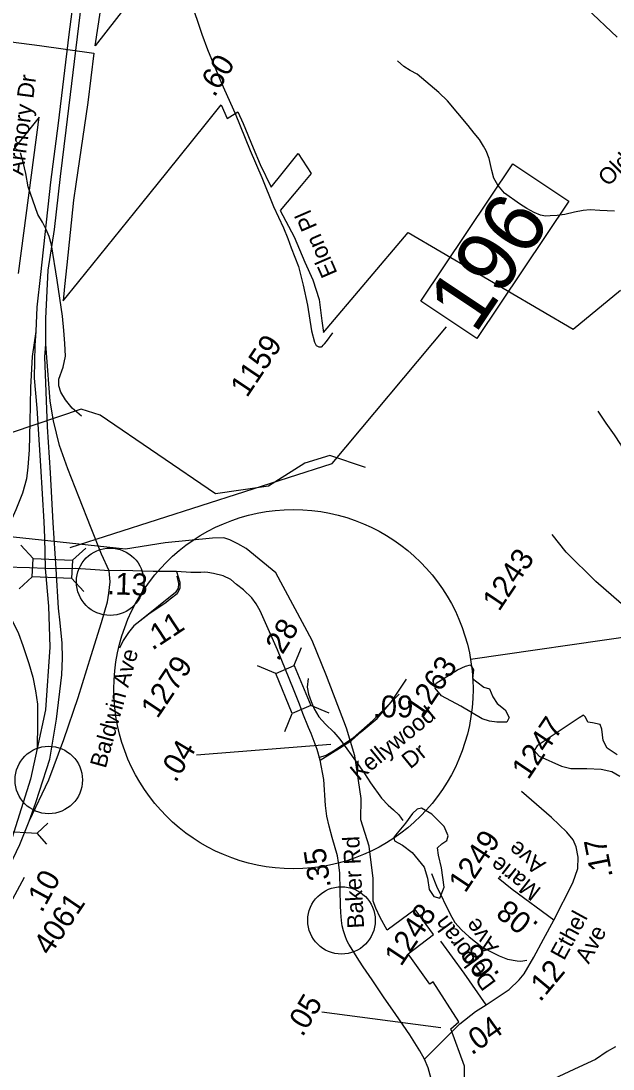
# Model space of a CAD drawing. Extents: x 1715610 to 1720914, y 798298 to 802505.
# Drawn here: x 1715906.1 to 1715979.8, y 799574.8 to 799705.3 of the extents above; entities that cross this region are included whole.
import ezdxf

# ---------------------------------------------------------------- set-up
doc = ezdxf.new("R2010")
doc.units = 0
doc.layers.add('Default', color=7, linetype='Continuous')
doc.layers.add('Prop DSN Text', color=7, linetype='Continuous')

msp = doc.modelspace()

# ---------------------------------------------------------------- linework, layer by layer
at = {"layer": 'Default'}
for p, q in [((1715906.08, 799640.03), (1715907.59, 799638.38)), ((1715912.49, 799638.15), (1715914.14, 799639.66)), ((1715905.84, 799634.58), (1715907.49, 799636.09)), ((1715912.39, 799635.91), (1715913.9, 799634.26)), ((1715940.08, 799625.02), (1715941.02, 799627.29)), ((1715937.81, 799624.07), (1715935.53, 799625.01)), ((1715938.93, 799616.81), (1715939.87, 799619.09)), ((1715944.47, 799619.12), (1715942.19, 799620.06)), ((1715944.68, 799615.21), (1715927.94, 799613.87)), ((1715909.43, 799605.42), (1715908.11, 799604.18)), ((1715903.81, 799604.43), (1715908.11, 799604.18)), ((1715909.28, 799602.8), (1715908.11, 799604.18)), ((1715958.35, 799579.93), (1715943.56, 799581.88))]:
    msp.add_line(p, q, dxfattribs=at)
for points in [[(1715915.87, 799731.82), (1715913.25, 799712.93), (1715912.04, 799703.65), (1715910.72, 799692.59), (1715909.75, 799685.23), (1715908.49, 799673.76), (1715908.04, 799669.68), (1715907.92, 799666.67)], [(1715909.16, 799665.06), (1715909.16, 799668.28), (1715909.48, 799674.3), (1715910.26, 799679.35), (1715910.99, 799685.96), (1715911.72, 799691.71), (1715914.34, 799713.3), (1715916.13, 799723.77)], [(1715921.67, 799710.42), (1715915.32, 799702.24), (1715915.3, 799702.21), (1715916.92, 799712.92)], [(1715921.67, 799710.42), (1715915.32, 799702.24), (1715915.3, 799702.21), (1715916.92, 799712.92)], [(1715927.44, 799707.09), (1715928.05, 799705.29), (1715928.59, 799703.69), (1715929.31, 799701.76), (1715931.05, 799697.56), (1715932.77, 799693.81), (1715934.63, 799689.21), (1715936.09, 799685.85), (1715937.54, 799682.23), (1715938.76, 799679.56), (1715939.33, 799678.24), (1715939.71, 799677.08), (1715940.66, 799674.75), (1715940.94, 799673.59), (1715941.24, 799672.42), (1715941.75, 799669.95), (1715942.25, 799666.72), (1715942.62, 799665.31), (1715942.84, 799664.92), (1715943.19, 799664.72), (1715943.49, 799664.76), (1715943.57, 799664.77), (1715943.72, 799664.94), (1715943.88, 799665.11), (1715944.13, 799665.4), (1715944.92, 799666.5)], [(1715980.31, 799703.3), (1715976.56, 799706.89)], [(1715980.31, 799703.3), (1715976.56, 799706.89)], [(1715900.95, 799703.22), (1715908.4, 799702.28), (1715915.17, 799701.33), (1715914.39, 799695.17), (1715912.92, 799684.99), (1715912.63, 799683), (1715911.79, 799674.96), (1715911.51, 799672.25), (1715911.35, 799670.45), (1715913.3, 799672.88), (1715921.12, 799682.58), (1715924.25, 799686.47), (1715929.19, 799692.6), (1715931.02, 799694.87), (1715931.77, 799693.17), (1715933.08, 799694), (1715933.73, 799692.54)], [(1715900.95, 799703.22), (1715908.4, 799702.28), (1715915.17, 799701.33), (1715914.39, 799695.17), (1715912.92, 799684.99), (1715912.63, 799683), (1715911.79, 799674.96), (1715911.51, 799672.25), (1715911.35, 799670.45), (1715913.3, 799672.88), (1715921.12, 799682.58), (1715924.25, 799686.47), (1715929.19, 799692.6), (1715931.02, 799694.87), (1715931.77, 799693.17), (1715933.08, 799694), (1715933.73, 799692.54)], [(1715980, 799681.64), (1715978.17, 799681.73), (1715976.96, 799681.82), (1715976.1, 799681.72), (1715975.01, 799681.51), (1715973.82, 799681.23), (1715972.87, 799681.08), (1715972, 799681.04), (1715971.41, 799681.03), (1715970.8, 799681.13), (1715969.98, 799681.48), (1715969.07, 799681.99), (1715968.15, 799682.57), (1715966.3, 799683.88), (1715965.46, 799684.88), (1715964.98, 799685.73), (1715964.7, 799686.71), (1715964.39, 799688.19), (1715964, 799689.15), (1715963.7, 799689.72), (1715963.17, 799690.56), (1715962.51, 799691.37), (1715961.78, 799692.3), (1715959.19, 799695.38), (1715958.12, 799696.43), (1715955.4, 799698.7), (1715954.56, 799699.17), (1715953.78, 799699.65), (1715952.96, 799700.38)], [(1715905.79, 799673.89), (1715908.36, 799693.36), (1715901.2, 799684.46)], [(1715905.79, 799673.89), (1715908.36, 799693.36), (1715901.2, 799684.46)], [(1715933.73, 799692.54), (1715934.99, 799689.52), (1715935.86, 799687.44), (1715937.23, 799684.61), (1715938.59, 799686.31), (1715940.6, 799688.83), (1715942.22, 799686.32), (1715940.97, 799684.83), (1715938.37, 799681.7), (1715940.12, 799678.46), (1715941.44, 799675.3), (1715942.44, 799673.08), (1715943.2, 799670.65), (1715943.54, 799667.97), (1715943.77, 799666.51), (1715954.32, 799678.97), (1715974.84, 799666.96), (1715980.75, 799671.8)], [(1715933.73, 799692.54), (1715934.99, 799689.52), (1715935.86, 799687.44), (1715937.23, 799684.61), (1715938.59, 799686.31), (1715940.6, 799688.83), (1715942.22, 799686.32), (1715940.97, 799684.83), (1715938.37, 799681.7), (1715940.12, 799678.46), (1715941.44, 799675.3), (1715942.44, 799673.08), (1715943.2, 799670.65), (1715943.54, 799667.97), (1715943.77, 799666.51), (1715954.32, 799678.97), (1715974.84, 799666.96), (1715980.75, 799671.8)], [(1715913.61, 799656.12), (1715912.45, 799657.12), (1715911.61, 799658.12), (1715911.05, 799659.08), (1715910.81, 799659.88), (1715910.8, 799660.72), (1715911.34, 799662.2), (1715911.64, 799663.57), (1715911.56, 799665.16), (1715911.41, 799666.79), (1715911.24, 799668.54), (1715910.58, 799673.05), (1715909.9, 799677.46), (1715909.59, 799678.47), (1715909.2, 799679.36), (1715908.75, 799680.25), (1715908.16, 799681.23), (1715906.98, 799684.67), (1715906.67, 799686.31), (1715906.34, 799687.75), (1715906.03, 799688.91)], [(1715912.21, 799639.76), (1715944.82, 799650.2), (1715959.07, 799667.23)], [(1715907.92, 799666.67), (1715907.49, 799663.53), (1715907.27, 799659.67), (1715907.19, 799655.36), (1715907.08, 799651.92), (1715906.95, 799649.74), (1715906.77, 799648.31), (1715906.28, 799646.53), (1715905.43, 799644.44), (1715903.95, 799641.06), (1715902.9, 799638.56), (1715902.3, 799637.29)], [(1715907.92, 799666.67), (1715907.82, 799664.89), (1715907.71, 799660.91), (1715907.71, 799660.85), (1715908.04, 799657.12), (1715908.52, 799649.92), (1715908.94, 799642.95), (1715908.99, 799641), (1715909.1, 799637.14)], [(1715910.48, 799637.07), (1715910.1, 799642.82), (1715909.77, 799649.03), (1715909.4, 799654.76), (1715909.04, 799663.48), (1715909.16, 799665.06)], [(1715917.05, 799636.84), (1715916.1, 799638.9), (1715914.82, 799642.14), (1715913.3, 799646.04), (1715911.9, 799649.55), (1715910.86, 799652.43), (1715910.11, 799655.51), (1715909.72, 799657.96), (1715909.58, 799659.61), (1715909.16, 799665.06)], [(1715948.98, 799649.69), (1715944.54, 799651.19), (1715941.43, 799650.24), (1715936.92, 799647.4), (1715930.32, 799646.42), (1715915.93, 799656.24), (1715913.57, 799656.98), (1715905, 799654.05), (1715901.6, 799656.26)], [(1715977.93, 799656.71), (1715978.93, 799655.23), (1715979.95, 799653.8), (1715980.75, 799652.57), (1715981.45, 799651.29), (1715982.12, 799650.11), (1715982.9, 799648.94), (1715984.73, 799646.53), (1715985.55, 799645.65), (1715986.49, 799644.7), (1715987.43, 799643.84), (1715988.29, 799643.25), (1715988.79, 799642.91), (1715989.21, 799642.36), (1715991.42, 799639.11), (1715992.82, 799636.84), (1715993.04, 799636.48), (1715993.83, 799635.94), (1715995.81, 799634.9), (1715996.8, 799634.49), (1715997.59, 799634.27), (1715998.12, 799633.96), (1715998.56, 799633.6)], [(1715961.41, 799569.63), (1715961.3, 799575.13), (1715959.6, 799579.81), (1715960.61, 799580.67), (1715957.42, 799585.64), (1715956.99, 799585.36), (1715954.31, 799589.15), (1715957.45, 799591.53), (1715955.16, 799594.67), (1715951.68, 799592.08), (1715950.8, 799593.68), (1715950.27, 799594.83), (1715949.94, 799595.71), (1715949.93, 799598.52), (1715949.46, 799602.56), (1715948.41, 799605.82), (1715948.43, 799608.5), (1715947.67, 799613.8), (1715946.6, 799617.23), (1715944.12, 799623.75), (1715942.35, 799628.18), (1715937.83, 799636.59), (1715934.11, 799639.61), (1715933.09, 799640.21), (1715932.08, 799640.69), (1715931.35, 799640.93), (1715929.92, 799640.91), (1715924.02, 799640.33), (1715919.1, 799639.53), (1715903.98, 799641.14)], [(1715961.41, 799569.63), (1715961.3, 799575.13), (1715959.6, 799579.81), (1715960.61, 799580.67), (1715957.42, 799585.64), (1715956.99, 799585.36), (1715954.31, 799589.15), (1715957.45, 799591.53), (1715955.16, 799594.67), (1715951.68, 799592.08), (1715950.8, 799593.68), (1715950.27, 799594.83), (1715949.94, 799595.71), (1715949.93, 799598.52), (1715949.46, 799602.56), (1715948.41, 799605.82), (1715948.43, 799608.5), (1715947.67, 799613.8), (1715946.6, 799617.23), (1715944.12, 799623.75), (1715942.35, 799628.18), (1715937.83, 799636.59), (1715934.11, 799639.61), (1715933.09, 799640.21), (1715932.08, 799640.69), (1715931.35, 799640.93), (1715929.92, 799640.91), (1715924.02, 799640.33), (1715919.1, 799639.53), (1715903.98, 799641.14)], [(1716000.83, 799614.29), (1715996.86, 799618.22), (1715990.88, 799623.76), (1715986.52, 799627.54), (1715980.85, 799632.71), (1715977.66, 799635.5), (1715973.98, 799639.15), (1715972.22, 799641.35)], [(1715902.3, 799637.29), (1715902.27, 799636.17), (1715904.22, 799632.17), (1715905.78, 799629.04), (1715906.3, 799627.55), (1715907.07, 799625.31), (1715907.56, 799623.59), (1715907.9, 799621.88), (1715908.13, 799620.24), (1715908.12, 799617.9), (1715908.1, 799614.72)], [(1715909.1, 799637.14), (1715907.16, 799637.22), (1715904.01, 799637.29), (1715902.3, 799637.29)], [(1715907.1, 799605.64), (1715907.91, 799607.98), (1715908.37, 799609.4), (1715909.68, 799613.37), (1715910.52, 799618.35), (1715911.17, 799623.87), (1715911.27, 799625.96), (1715911.22, 799627.81), (1715910.94, 799630.37), (1715910.74, 799632.19), (1715910.48, 799637.07)], [(1715907.1, 799605.64), (1715909.54, 799610.79), (1715911.43, 799615.84), (1715913.2, 799621.06), (1715914.83, 799626.29), (1715916.12, 799630.42), (1715916.85, 799632.97), (1715917, 799634.04), (1715917.18, 799635.48), (1715917.05, 799636.84)], [(1715909.1, 799637.14), (1715909.5, 799632.43), (1715909.66, 799627.33), (1715909.13, 799619.53), (1715908.1, 799614.72)], [(1715910.48, 799637.07), (1715909.1, 799637.14)], [(1715917.05, 799636.84), (1715914.72, 799637.01), (1715912.87, 799637.11), (1715910.48, 799637.07)], [(1715925.45, 799636.74), (1715922.55, 799636.75), (1715920.02, 799636.85), (1715918.47, 799636.9), (1715917.05, 799636.84)], [(1715925.45, 799636.74), (1715925.87, 799635.44), (1715925.85, 799634.67), (1715925.51, 799633.97), (1715924.67, 799633.31), (1715924.16, 799632.89), (1715921.99, 799631.46), (1715920.15, 799629.99), (1715919.45, 799629.17), (1715918.79, 799628.18), (1715918.34, 799627.19)], [(1715925.5, 799636.16), (1715925.7, 799635.28), (1715925.64, 799634.7), (1715925.31, 799634.14), (1715920.89, 799630.59)], [(1715940.01, 799622.1), (1715938.02, 799626.99), (1715936.68, 799629.97), (1715935.86, 799631.86), (1715935.37, 799632.74), (1715934.85, 799633.48), (1715933.8, 799634.46), (1715932.91, 799635.12), (1715932.21, 799635.76), (1715931.25, 799636.22), (1715930.05, 799636.52), (1715929.34, 799636.64), (1715928.97, 799636.67), (1715928.48, 799636.64), (1715927.23, 799636.65), (1715925.45, 799636.74)], [(1715963.51, 799618.41), (1715960.84, 799620), (1715958.46, 799621.29), (1715957.67, 799622.22), (1715957.79, 799622.85), (1715960.43, 799624.52), (1715961.43, 799624.97), (1715962.06, 799625.15), (1715962.43, 799624.5), (1715962.33, 799623.45), (1715962.85, 799623), (1715963.71, 799622.33), (1715964.41, 799622.16), (1715964.85, 799621.16), (1715965.38, 799620.3), (1715966.38, 799619.52), (1715966.87, 799618.59), (1715966.57, 799617.98), (1715965.35, 799617.99), (1715964.42, 799618.1), (1715963.51, 799618.41)], [(1715941.83, 799623.45), (1715941.72, 799622.37), (1715941.9, 799621.46), (1715942.22, 799620.55), (1715942.61, 799619.66), (1715943.18, 799618.64), (1715944, 799617.76), (1715945.04, 799616.73), (1715945.77, 799615.87), (1715948.08, 799612.7), (1715948.86, 799611.59), (1715949.6, 799610.45), (1715950.97, 799608.52), (1715951.79, 799607.64), (1715952.46, 799607.08), (1715953.14, 799606.46), (1715953.44, 799606.04), (1715953.65, 799605.74)], [(1715943.36, 799613.25), (1715945.76, 799614.74), (1715947.26, 799615.69), (1715948.45, 799616.77), (1715950.44, 799618.45), (1715952.17, 799620.48), (1715954.09, 799623.35)], [(1715943.36, 799613.25), (1715942.98, 799614.58), (1715942.21, 799616.56), (1715941.88, 799617.34), (1715941.18, 799619.08), (1715940.76, 799620.24), (1715940.01, 799622.1)], [(1715943.18, 799613.59), (1715944.1, 799613.89), (1715945.01, 799614.42), (1715947.44, 799616.05), (1715949.88, 799618.19), (1715953.16, 799621.46)], [(1715975.61, 799618.51), (1715970.36, 799615.04), (1715969.99, 799614.48), (1715970.62, 799613.76), (1715973.41, 799612.49), (1715974.55, 799612.24), (1715976.56, 799612.21), (1715978.33, 799612.14), (1715979.66, 799611.85), (1715980.68, 799611.27)], [(1715980.34, 799613.93), (1715979.08, 799614.77), (1715978.59, 799615.7), (1715978.43, 799617.13), (1715978.2, 799617.69), (1715977.25, 799617.92), (1715976.69, 799617.99), (1715976.38, 799618.6), (1715976.15, 799618.86), (1715975.61, 799618.51)], [(1715908.1, 799614.72), (1715907.27, 799610.89), (1715905.2, 799604.27), (1715904.99, 799603.62), (1715904.04, 799601.32), (1715902.16, 799597.57), (1715899.93, 799593.67), (1715899.17, 799592.53), (1715894.28, 799584.71), (1715890.45, 799578.48), (1715889, 799575.97), (1715887.67, 799573.62), (1715885.98, 799570.08), (1715884.37, 799565.77)], [(1715956.35, 799576.01), (1715955.77, 799577.07), (1715954.5, 799579.03), (1715952.76, 799581.58), (1715951.21, 799583.77), (1715949.81, 799585.88), (1715948.68, 799587.53), (1715948.23, 799588.22), (1715946.91, 799590.32), (1715946.67, 799590.78), (1715946.44, 799591.39), (1715946.26, 799591.99), (1715946.1, 799592.62), (1715946, 799593.3), (1715945.91, 799594.3), (1715945.87, 799595.15), (1715945.85, 799597.08), (1715945.77, 799599.24), (1715945.61, 799600.5), (1715945.48, 799601.36), (1715944.85, 799603.64), (1715944.45, 799605.04), (1715944.15, 799606.27), (1715944, 799607.61), (1715943.81, 799610.83), (1715943.36, 799613.25)], [(1715972.45, 799593.31), (1715974.79, 799598), (1715975.41, 799599.75), (1715975.49, 799601.17), (1715975.24, 799602.45), (1715974.85, 799603.33), (1715974.07, 799604.28), (1715972.15, 799606.12), (1715968.41, 799609.36)], [(1715953.98, 799605.42), (1715952.72, 799603.93), (1715952.51, 799603.61), (1715952.58, 799603.23), (1715953.61, 799602.68), (1715954.78, 799601.76), (1715956.29, 799599.95), (1715956.69, 799598.56), (1715956.93, 799597.13), (1715957.49, 799596.29), (1715958.26, 799596.05), (1715958.78, 799597.42), (1715958.46, 799599.83), (1715958.07, 799601.42), (1715957.97, 799602.35), (1715958.5, 799602.85), (1715959.1, 799603.25), (1715959.3, 799603.85), (1715958.8, 799604.98), (1715957.25, 799606.54), (1715955.96, 799607.28), (1715955.42, 799607.17), (1715954.85, 799606.62), (1715953.98, 799605.42)], [(1715899.04, 799589.96), (1715901.79, 799594.58), (1715904.25, 799599.2), (1715905.93, 799602.77), (1715907.1, 799605.64)], [(1715906.49, 799598.65), (1715902.96, 799592.16), (1715901.9, 799590.2), (1715901.52, 799589.64), (1715901.01, 799589.26), (1715900.51, 799589.04)], [(1715957.21, 799599.14), (1715957.82, 799597.57), (1715959.54, 799594.07), (1715960.11, 799593.05), (1715960.95, 799592.11), (1715961.89, 799591.26), (1715963.47, 799590.02), (1715964.45, 799589.45), (1715965.65, 799588.9), (1715966.67, 799588.46), (1715967.87, 799588.28), (1715968.35, 799588.22), (1715969.07, 799588.35)], [(1715972.45, 799593.31), (1715967.26, 799597.15), (1715965.5, 799598.57)], [(1715964.03, 799582.78), (1715966.88, 799584.71), (1715968.12, 799585.91), (1715968.74, 799586.66), (1715969.93, 799588.71), (1715971.14, 799590.98), (1715972.45, 799593.31)], [(1715964.03, 799582.78), (1715961.27, 799586.73), (1715958.38, 799590.7)], [(1715956.35, 799576.01), (1715960.73, 799580.41), (1715962.68, 799581.95), (1715964.03, 799582.78)], [(1715980.11, 799577.56), (1715979.1, 799576.96), (1715977.64, 799575.97), (1715975.57, 799575.01), (1715972.43, 799573.56)], [(1715957.3, 799567), (1715957.34, 799570.54), (1715957.27, 799572.46), (1715957.15, 799573.55), (1715956.78, 799574.94), (1715956.35, 799576.01)]]:
    msp.add_lwpolyline(points, dxfattribs=at)
for points in [[(1715955.88, 799670.44), (1715967.33, 799687.55), (1715974.32, 799682.88), (1715962.87, 799665.77)], [(1715907.59, 799638.38), (1715912.49, 799638.16), (1715912.39, 799635.87), (1715907.49, 799636.09)], [(1715939.87, 799619.09), (1715937.8, 799624.06), (1715940.12, 799625.03), (1715942.19, 799620.06)]]:
    msp.add_lwpolyline(points, close=True, dxfattribs=at)
msp.add_circle((1715940.01, 799622.1), 22.37, dxfattribs=at)
at = {"layer": 'Prop DSN Text'}
msp.add_line((1716020.09, 799634.2), (1715962.07, 799625.8), dxfattribs=at)
for centre in [(1715917.18, 799635.48), (1715909.54, 799610.79), (1715946, 799593.3)]:
    msp.add_circle(centre, 4.2, dxfattribs=at)

# ---------------------------------------------------------------- texts
at = {"layer": 'Default'}
for s, height, rotation, p in [('Old Jackson Lake Rd', 2.0663, 45.2182, (1715979.19, 799684.62)), ('.60', 2.719, 58.4296, (1715930.17, 799695.73)), ('Armory Dr', 2.066, 82.5782, (1715906.36, 799686.01)), ('196', 7.613, 56.2051, (1715962.66, 799666.23)), ('Elon Pl', 2.066, 113.4495, (1715945.52, 799673.92)), ('1159', 2.719, 56.2051, (1715934.22, 799658.32)), ('1243', 2.719, 56.2051, (1715965.62, 799631.68)), ('.13', 2.719, 358.1259, (1715916.77, 799633.93)), ('.11', 2.719, 33.3761, (1715922.44, 799626.87)), ('.28', 2.719, 57.9606, (1715938.11, 799625.47)), ('Baldwin Ave', 2.0663, 74.4007, (1715916.62, 799612.15)), ('1279', 2.719, 56.2051, (1715923.07, 799618.33)), ('1263', 2.719, 56.2051, (1715956.02, 799618.29)), ('.09', 2.719, 359.976, (1715949.88, 799618.59)), ('Kellywood', 2.066, 39.3204, (1715948.14, 799610.6)), ('1247', 2.719, 56.2051, (1715969.26, 799610.72)), ('.04', 2.719, 58.9616, (1715925.35, 799610.36)), (' Dr', 2.066, 39.3204, (1715953.96, 799611.6)), ('Baker Rd', 2.066, 93.0822, (1715948.82, 799592.35)), ('1249', 2.719, 56.2051, (1715961.4, 799596.61)), (' Ave', 2.066, 141.9396, (1715972.16, 799599.99)), ('.35', 2.719, 98.5855, (1715944.69, 799597.47)), ('.17', 2.719, 101.1829, (1715979.8, 799598.78)), ('Marie', 2.066, 141.9396, (1715970.99, 799597.21)), ('.10', 2.719, 61.4147, (1715908.68, 799594.15)), ('4061', 2.719, 56.2051, (1715909.69, 799588.8)), ('.08', 2.719, 141.0065, (1715970.68, 799592.87)), ('1248', 2.719, 56.2051, (1715953.41, 799587.46)), ('Ethel', 2.066, 61.3686, (1715973.71, 799588.21)), ('Deborah', 2.066, 126.3304, (1715965.33, 799585.55)), (' Ave', 2.066, 126.3304, (1715966.13, 799589.37)), (' Ave', 2.066, 61.3686, (1715976.42, 799587.1)), ('.08', 2.719, 124.9147, (1715965.77, 799586.55)), ('.12', 2.719, 50.2009, (1715970.74, 799583.05)), ('.05', 2.719, 59.3208, (1715941.14, 799578.69)), ('.04 ', 2.719, 35.5211, (1715962.21, 799576.45))]:
    msp.add_text(s, height=height, rotation=rotation, dxfattribs=at).set_placement(p)

doc.saveas('drawing.dxf')
